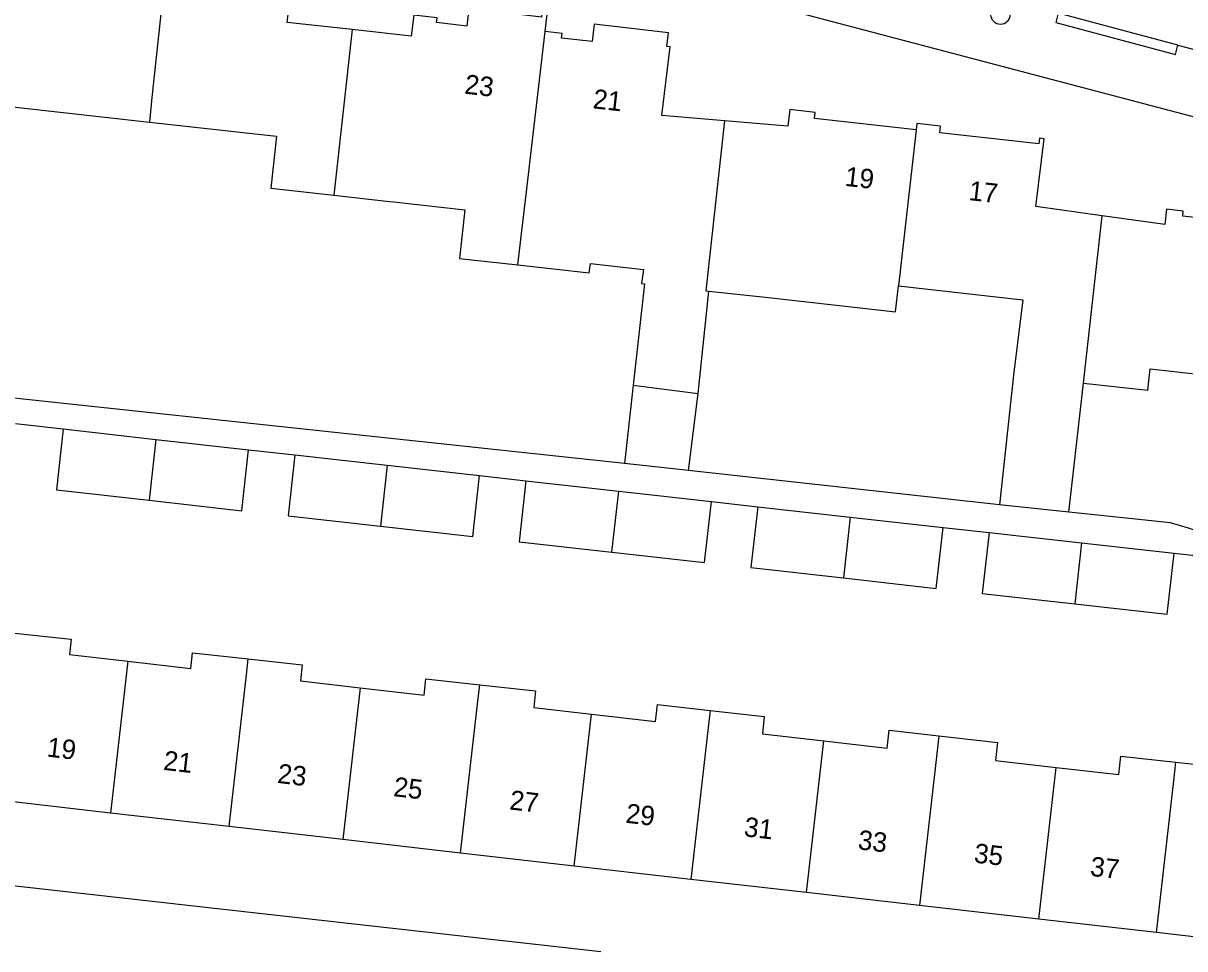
# Model space of a CAD drawing. Extents: x 162026 to 163499, y 387297 to 388169.
# Drawn here: x 162383.6 to 162443.5, y 387907.4 to 387955.1 of the extents above; entities that cross this region are included whole.
import ezdxf

# ---------------------------------------------------------------- set-up
doc = ezdxf.new("R2010")
doc.units = 0
for name, color, linetype in [('IMGEO_Boom', 7, 'Continuous'), ('IMGEO_Pand', 7, 'Continuous'), ('IMGEO_Pand_nummerreeks', 7, 'Continuous'), ('IMGEO_Rijbaan_lokaal_open', 7, 'Continuous'), ('IMGEO_Voetpad_open', 7, 'Continuous')]:
    doc.layers.add(name, color=color, linetype=linetype)

msp = doc.modelspace()

# ---------------------------------------------------------------- linework, layer by layer
at = {"layer": 'IMGEO_Boom'}
msp.add_circle((162433.954, 387955.513), 0.489, dxfattribs=at)
at = {"layer": 'IMGEO_Pand'}
for points in [[(162391.105, 387959.57), (162390.215, 387951.26), (162390.08, 387949.995)], [(162400.537, 387954.756), (162397.192, 387955.12), (162397.623, 387958.824), (162397.364, 387958.854), (162397.338, 387958.635), (162392.083, 387959.246), (162392.107, 387959.454), (162391.105, 387959.57)], [(162410.482, 387954.661), (162410.586, 387955.552), (162410.314, 387955.583), (162410.293, 387955.403), (162406.554, 387955.839), (162406.448, 387954.937), (162404.884, 387955.119), (162404.911, 387955.359), (162403.708, 387955.499), (162403.582, 387954.425), (162400.537, 387954.756)], [(162400.537, 387954.756), (162399.593, 387946.219)], [(162419.735, 387950.059), (162416.499, 387950.328), (162416.925, 387953.872), (162416.764, 387953.89), (162416.846, 387954.591), (162413.007, 387955.039), (162412.901, 387954.136), (162411.327, 387954.32), (162411.354, 387954.56), (162410.482, 387954.661)], [(162409.082, 387942.636), (162409.505, 387946.268), (162410.482, 387954.661)], [(162380.31, 387951.077), (162383.337, 387950.742), (162390.08, 387949.995)], [(162429.615, 387949.598), (162424.369, 387950.179), (162424.403, 387950.487), (162423.088, 387950.633), (162422.994, 387949.789), (162419.735, 387950.059)], [(162390.08, 387949.995), (162396.639, 387949.268), (162396.341, 387946.579), (162399.593, 387946.219)], [(162419.735, 387950.059), (162418.765, 387941.306), (162418.918, 387941.289)], [(162429.615, 387949.598), (162428.692, 387941.552)], [(162439.191, 387945.165), (162435.778, 387945.647), (162436.207, 387949.13), (162435.961, 387949.158), (162435.93, 387948.874), (162430.824, 387949.439), (162430.861, 387949.78), (162429.65, 387949.914), (162429.615, 387949.598)], [(162399.593, 387946.219), (162402.451, 387945.903), (162402.68, 387945.878), (162406.342, 387945.473), (162406.065, 387942.97), (162409.082, 387942.636)], [(162438.23, 387936.546), (162439.191, 387945.165)], [(162449.124, 387944.508), (162443.353, 387945.147), (162443.381, 387945.407), (162442.515, 387945.503), (162442.427, 387944.708), (162439.191, 387945.165)], [(162409.082, 387942.636), (162412.76, 387942.229), (162412.813, 387942.706), (162415.546, 387942.403), (162415.458, 387941.672), (162415.604, 387941.656), (162415.026, 387936.433)], [(162418.378, 387936.003), (162418.918, 387941.289)], [(162418.918, 387941.289), (162421.989, 387940.949), (162428.545, 387940.223), (162428.692, 387941.552)], [(162428.692, 387941.552), (162435.114, 387940.84), (162434.635, 387936.945), (162433.91, 387930.276)], [(162438.23, 387936.546), (162441.553, 387936.178), (162441.675, 387937.277), (162444.899, 387936.92), (162444.811, 387936.136), (162448.138, 387935.761), (162448.227, 387936.551)], [(162415.026, 387936.433), (162414.58, 387932.402)], [(162415.026, 387936.433), (162418.378, 387936.003)], [(162437.481, 387929.887), (162438.23, 387936.546)], [(162417.87, 387932.043), (162418.378, 387936.003)], [(162385.635, 387934.182), (162385.284, 387931.042), (162390.064, 387930.507)], [(162385.635, 387934.182), (162390.415, 387933.647)], [(162390.415, 387933.647), (162390.064, 387930.507)], [(162390.415, 387933.647), (162395.195, 387933.113)], [(162390.064, 387930.507), (162394.844, 387929.972), (162395.195, 387933.113)], [(162397.58, 387932.846), (162397.229, 387929.706), (162401.99, 387929.173)], [(162397.58, 387932.846), (162402.341, 387932.314)], [(162402.341, 387932.314), (162401.99, 387929.173)], [(162402.341, 387932.314), (162407.101, 387931.781)], [(162417.87, 387932.043), (162414.58, 387932.402)], [(162401.99, 387929.173), (162406.75, 387928.641), (162407.101, 387931.781)], [(162409.495, 387931.514), (162409.144, 387928.373), (162413.924, 387927.839)], [(162409.495, 387931.514), (162414.275, 387930.979)], [(162413.924, 387927.839), (162414.275, 387930.979)], [(162414.275, 387930.979), (162419.056, 387930.444)], [(162413.924, 387927.839), (162418.705, 387927.304), (162419.056, 387930.444)], [(162437.481, 387929.887), (162433.91, 387930.276)], [(162421.442, 387930.178), (162421.09, 387927.037), (162425.861, 387926.504)], [(162421.442, 387930.178), (162426.212, 387929.644)], [(162426.212, 387929.644), (162425.861, 387926.504)], [(162426.212, 387929.644), (162430.997, 387929.109)], [(162425.861, 387926.504), (162430.646, 387925.969), (162430.997, 387929.109)], [(162433.364, 387928.844), (162433.013, 387925.704), (162437.783, 387925.17)], [(162433.364, 387928.844), (162438.134, 387928.311)], [(162438.134, 387928.311), (162437.783, 387925.17)], [(162438.134, 387928.311), (162442.902, 387927.778)], [(162437.783, 387925.17), (162442.552, 387924.637), (162442.902, 387927.778)], [(162383.144, 387923.67), (162386.041, 387923.347), (162385.954, 387922.559), (162388.965, 387922.215)], [(162388.965, 387922.215), (162392.213, 387921.844), (162392.303, 387922.651), (162395.178, 387922.331)], [(162388.965, 387922.215), (162388.072, 387914.393)], [(162394.191, 387913.694), (162395.085, 387921.516), (162395.178, 387922.331)], [(162395.178, 387922.331), (162397.959, 387922.022), (162397.867, 387921.198), (162400.952, 387920.846)], [(162400.952, 387920.846), (162404.242, 387920.47), (162404.335, 387921.313), (162407.112, 387921.004)], [(162400.952, 387920.846), (162400.059, 387913.024)], [(162406.122, 387912.331), (162407.015, 387920.153), (162407.112, 387921.004)], [(162407.112, 387921.004), (162409.992, 387920.684), (162409.896, 387919.824), (162412.878, 387919.483)], [(162411.985, 387911.661), (162412.878, 387919.483)], [(162412.878, 387919.483), (162416.172, 387919.107), (162416.269, 387919.986), (162418.99, 387919.683)], [(162418.99, 387919.683), (162418.889, 387918.796), (162417.995, 387910.974)], [(162418.99, 387919.683), (162421.781, 387919.373), (162421.681, 387918.477), (162424.855, 387918.115)], [(162424.855, 387918.115), (162428.111, 387917.743), (162428.213, 387918.658), (162430.773, 387918.373)], [(162430.773, 387918.373), (162430.668, 387917.451), (162429.774, 387909.629)], [(162430.773, 387918.373), (162433.803, 387918.036), (162433.699, 387917.105), (162436.832, 387916.747)], [(162423.961, 387910.293), (162424.855, 387918.115)], [(162436.832, 387916.747), (162440.049, 387916.379), (162440.157, 387917.33), (162443.003, 387917.013)], [(162435.938, 387908.925), (162436.832, 387916.747)], [(162443.003, 387917.013), (162445.667, 387916.717), (162445.559, 387915.749), (162448.951, 387915.362), (162448.625, 387912.508), (162448.057, 387907.54), (162442, 387908.232)], [(162442, 387908.232), (162442.893, 387916.054), (162443.003, 387917.013)], [(162388.072, 387914.393), (162382.162, 387915.068)], [(162394.191, 387913.694), (162388.072, 387914.393)], [(162400.059, 387913.024), (162394.191, 387913.694)], [(162406.122, 387912.331), (162400.059, 387913.024)], [(162411.985, 387911.661), (162406.122, 387912.331)], [(162417.995, 387910.974), (162411.985, 387911.661)], [(162423.961, 387910.293), (162417.995, 387910.974)], [(162429.774, 387909.629), (162423.961, 387910.293)], [(162435.938, 387908.925), (162429.774, 387909.629)], [(162442, 387908.232), (162435.938, 387908.925)]]:
    msp.add_lwpolyline(points, dxfattribs=at)
at = {"layer": 'IMGEO_Rijbaan_lokaal_open'}
for points in [[(162443.098, 387953.956), (162436.937, 387955.599)], [(162443.098, 387953.956), (162445.905, 387953.208)]]:
    msp.add_lwpolyline(points, dxfattribs=at)
at = {"layer": 'IMGEO_Voetpad_open'}
for points in [[(162385.229, 387965.736), (162453.931, 387947.627), (162456.374, 387947.084), (162458.852, 387946.73), (162500, 387942.464), (162503.264, 387942.125)], [(162436.937, 387955.599), (162436.812, 387955.115), (162442.973, 387953.472), (162443.098, 387953.956)], [(162414.58, 387932.402), (162376.968, 387936.428)], [(162383.185, 387934.456), (162385.635, 387934.182)], [(162395.195, 387933.113), (162397.58, 387932.846)], [(162433.91, 387930.276), (162417.87, 387932.043)], [(162407.101, 387931.781), (162409.495, 387931.514)], [(162419.056, 387930.444), (162421.442, 387930.178)], [(162452.707, 387914.299), (162452.427, 387914.332), (162453.507, 387924.369), (162446.336, 387927.972), (162445.457, 387928.385), (162444.385, 387928.824), (162443.646, 387929.073), (162442.716, 387929.353), (162437.481, 387929.887)], [(162430.997, 387929.109), (162433.364, 387928.844)], [(162442.902, 387927.778), (162443.831, 387927.674), (162451.562, 387923.911)], [(162378.114, 387911.206), (162413.36, 387907.265)]]:
    msp.add_lwpolyline(points, dxfattribs=at)

# ---------------------------------------------------------------- texts
at = {"layer": 'IMGEO_Pand_nummerreeks'}
for s, rotation, p in [('23', 353.68601, (162406.295, 387951.46)), ('21', 353.68601, (162412.91, 387950.706)), ('19', 353.68028, (162425.901, 387946.71)), ('17', 353.68601, (162432.286, 387945.978)), ('19', 353.47974, (162384.763, 387917.308)), ('21', 353.47974, (162390.77, 387916.622)), ('23', 353.47974, (162396.644, 387915.951)), ('25', 353.47974, (162402.63, 387915.267)), ('27', 353.47974, (162408.615, 387914.583)), ('29', 353.47974, (162414.601, 387913.899)), ('31', 353.47974, (162420.699, 387913.203)), ('33', 353.47974, (162426.572, 387912.532)), ('35', 353.47974, (162432.558, 387911.848)), ('37', 353.47974, (162438.544, 387911.164))]:
    msp.add_text(s, height=1, rotation=rotation, dxfattribs=at).set_placement(p)

doc.saveas('drawing.dxf')
